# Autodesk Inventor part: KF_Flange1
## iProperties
Created: 2006-07
Part Number: KF_Flange1
Document SubType Name: Modeling
Designer: Administrator
Author: Administrator
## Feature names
1. Extrusion1
2. Extrusion2
3. Revolution1
4. Revolution2
